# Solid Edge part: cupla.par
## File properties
Author: Ionut
Template: Normal.par
Last saved by: Ionut
Revision: 4
Application: Solid Edge
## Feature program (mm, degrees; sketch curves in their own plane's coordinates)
sketch for "unnamed Protrusion 1" plane through (0, 0, 0) normal (0, 0, 1) x-axis (1, 0, 0)
  circle centre (0, 0) radius 6
extrude "unnamed Protrusion 1" add finite 12 along +normal
sketch for "unnamed Hole 1" plane through (0, 0, 12) normal (0, 0, 1) x-axis (0, 1, 0)
  hole centre (0, 0) bore radius 5
hole "unnamed Hole 1" through
sketch for "unnamed Protrusion 2" #1 plane through (0, 0, 0) normal (0, -1, 0) x-axis (1, 0, 0)
  circle centre (-9, 6) radius 1.5
sketch for "unnamed Protrusion 2" #2 plane through (0, 0, 0) normal (0, -1, 0) x-axis (1, 0, 0)
  line (-11, 3) -> (-5, 3)
  line (-5, 3) -> (-5, 9)
  line (-5, 9) -> (-11, 9)
  line (-11, 9) -> (-11, 3)
extrude "unnamed Protrusion 2" add finite 4 symmetric
sketch for "unnamed Cutout 1" plane through (-8.3284, 0, 3) normal (0, 0, -1) x-axis (0, -1, 0)
  line (-0.8, -1.3284) -> (0.8, -1.3284)
  line (0.8, -1.3284) -> (0.8, 2.6716)
  line (0.8, 2.6716) -> (-0.8, 2.6716)
  line (-0.8, 2.6716) -> (-0.8, -1.3284)
extrude "unnamed Cutout 1" cut through along -normal
fillet "unnamed Round 1"
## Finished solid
Body 1: solid body, 19 faces, 44 edges, 24 vertices.
  Faces by surface: plane 11, cylinder 8
  Edges by curve: line 26, circle 18
Bounding box of the edges (mm): 17.000 x 12.000 x 12.000, from (-11, -6, 0) to (6, 6, 12).
Cylindrical faces by radius (mm): R1.5 x2, R2 x4, R5 x1, R6 x1
Planar faces by outward normal: +y 2, +z 2, -x 3, -y 2, -z 2
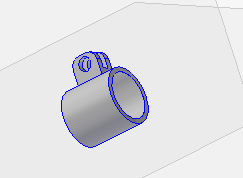
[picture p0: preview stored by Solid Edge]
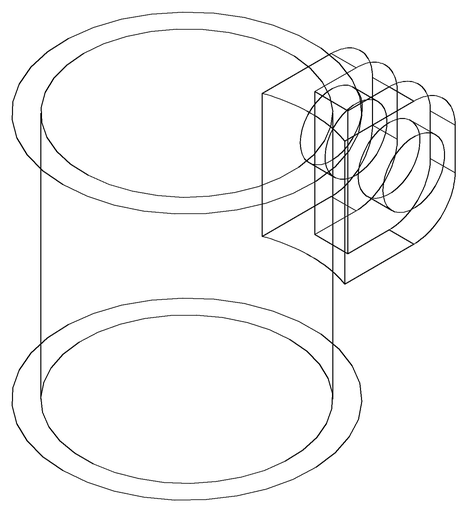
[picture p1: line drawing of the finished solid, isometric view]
